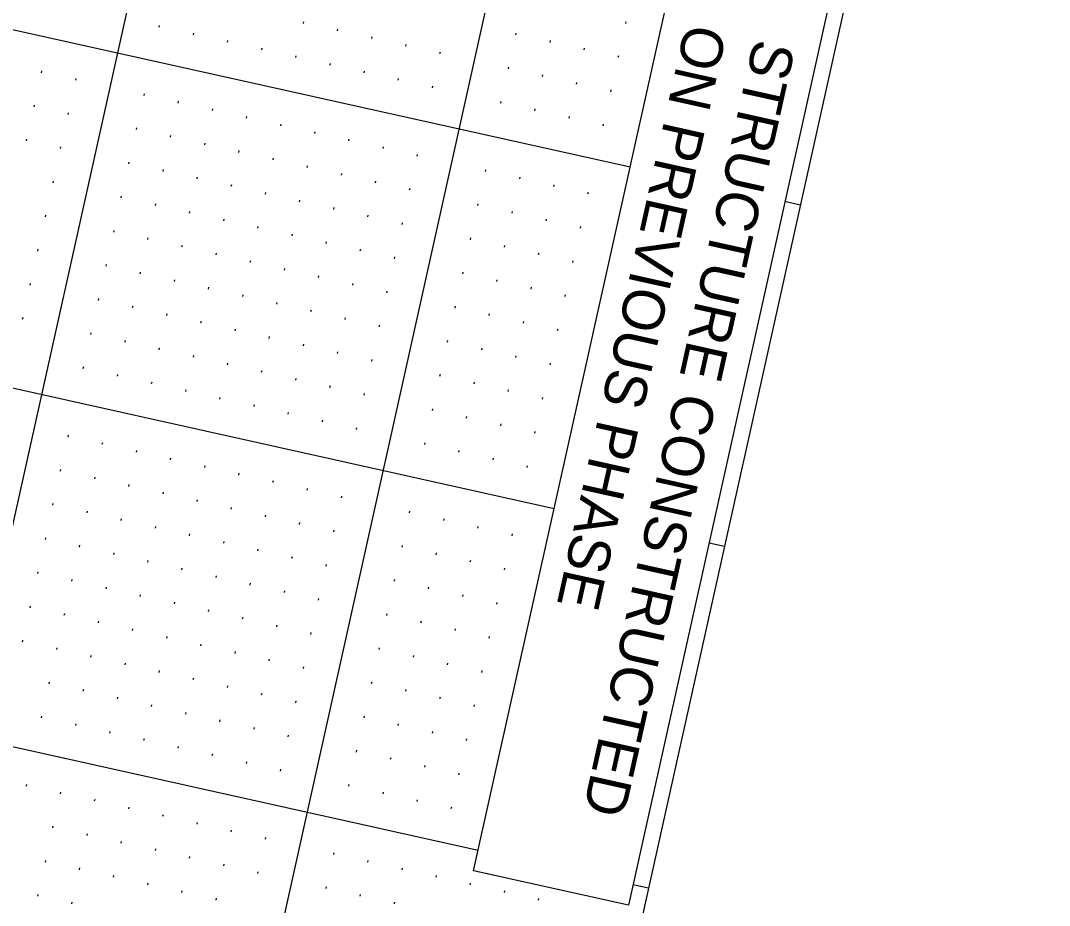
# Model space of a CAD drawing. Extents: x 2149268 to 2150830, y 142155 to 144285.
# Drawn here: x 2149816 to 2149963, y 142509.8 to 142636.2 of the extents above; entities that cross this region are included whole.
import ezdxf

# ---------------------------------------------------------------- set-up
doc = ezdxf.new("R2010")
doc.units = 0
for name, color, linetype in [('PR_Grading_Txt', 7, 'Continuous'), ('PR_Misc_Improvement', 7, 'Continuous'), ('SHT_Profile_Grid_Major', 7, 'Continuous'), ('SHT_Profile_Grid_Minor', 7, 'Continuous'), ('SHT_Sheet_Border', 7, 'Continuous')]:
    doc.layers.add(name, color=color, linetype=linetype)

msp = doc.modelspace()

# ---------------------------------------------------------------- linework, layer by layer
at = {"layer": 'PR_Misc_Improvement'}
msp.add_lwpolyline([(2149936.73, 142662.14), (2149902.85, 142509.8), (2149880.72, 142514.72), (2149914.6, 142667.07)], close=True, dxfattribs=at)
at = {"layer": 'SHT_Profile_Grid_Major'}
for p, q in [((2150109.25, 143888.4), (2149767.39, 142350.95)), ((2150158.06, 143877.55), (2149816.2, 142340.1)), ((2149439.33, 142718.42), (2149903.09, 142615.3)), ((2149452.88, 142664.18), (2149892.23, 142566.49)), ((2149442.03, 142615.38), (2149881.38, 142517.68)), ((2149925.22, 142610.38), (2149927.41, 142609.89)), ((2149914.37, 142561.57), (2149916.56, 142561.08)), ((2149903.51, 142512.76), (2149905.7, 142512.27))]:
    msp.add_line(p, q, dxfattribs=at)
at = {"layer": 'SHT_Profile_Grid_Minor'}
for p, q in [((2149856.4, 142636.05), (2149856.34, 142635.81)), ((2149902.49, 142636.05), (2149902.44, 142635.8)), ((2149835.79, 142635.51), (2149835.73, 142635.27)), ((2149861.28, 142634.97), (2149861.22, 142634.72)), ((2149840.67, 142634.43), (2149840.61, 142634.18)), ((2149845.55, 142633.34), (2149845.49, 142633.1)), ((2149866.16, 142633.88), (2149866.1, 142633.64)), ((2149886.77, 142634.42), (2149886.71, 142634.18)), ((2149891.65, 142633.34), (2149891.59, 142633.09)), ((2149850.43, 142632.26), (2149850.38, 142632.01)), ((2149871.04, 142632.8), (2149870.98, 142632.55)), ((2149875.92, 142631.71), (2149875.86, 142631.47)), ((2149896.53, 142632.25), (2149896.47, 142632.01)), ((2149855.31, 142631.17), (2149855.26, 142630.93)), ((2149901.41, 142631.17), (2149901.35, 142630.92)), ((2149818.97, 142629.01), (2149818.92, 142628.76)), ((2149860.19, 142630.09), (2149860.14, 142629.84)), ((2149865.07, 142629), (2149865.02, 142628.76)), ((2149885.68, 142629.54), (2149885.63, 142629.3)), ((2149823.86, 142627.92), (2149823.8, 142627.68)), ((2149869.95, 142627.92), (2149869.9, 142627.67)), ((2149890.56, 142628.46), (2149890.51, 142628.21)), ((2149895.44, 142627.37), (2149895.39, 142627.13)), ((2149833.62, 142625.75), (2149833.56, 142625.51)), ((2149874.83, 142626.83), (2149874.78, 142626.59)), ((2149900.32, 142626.29), (2149900.27, 142626.04)), ((2149838.5, 142624.67), (2149838.44, 142624.42)), ((2149884.6, 142624.66), (2149884.54, 142624.42)), ((2149817.89, 142624.13), (2149817.84, 142623.88)), ((2149822.77, 142623.04), (2149822.72, 142622.8)), ((2149843.38, 142623.58), (2149843.32, 142623.34)), ((2149889.48, 142623.58), (2149889.42, 142623.33)), ((2149848.26, 142622.5), (2149848.21, 142622.25)), ((2149853.14, 142621.41), (2149853.09, 142621.17)), ((2149894.36, 142622.49), (2149894.3, 142622.25)), ((2149899.24, 142621.41), (2149899.18, 142621.16)), ((2149832.53, 142620.87), (2149832.48, 142620.63)), ((2149858.02, 142620.33), (2149857.97, 142620.08)), ((2149816.8, 142619.25), (2149816.75, 142619)), ((2149837.41, 142619.79), (2149837.36, 142619.54)), ((2149842.29, 142618.7), (2149842.24, 142618.46)), ((2149862.9, 142619.24), (2149862.85, 142619)), ((2149821.68, 142618.16), (2149821.63, 142617.92)), ((2149847.17, 142617.62), (2149847.12, 142617.37)), ((2149867.78, 142618.16), (2149867.73, 142617.91)), ((2149872.66, 142617.07), (2149872.61, 142616.83)), ((2149831.45, 142615.99), (2149831.39, 142615.75)), ((2149852.05, 142616.53), (2149852, 142616.29)), ((2149856.94, 142615.44), (2149856.88, 142615.2)), ((2149836.33, 142614.91), (2149836.27, 142614.66)), ((2149861.82, 142614.36), (2149861.76, 142614.12)), ((2149882.43, 142614.9), (2149882.37, 142614.66)), ((2149820.6, 142613.28), (2149820.55, 142613.04)), ((2149841.21, 142613.82), (2149841.15, 142613.58)), ((2149846.09, 142612.73), (2149846.03, 142612.49)), ((2149866.7, 142613.27), (2149866.64, 142613.03)), ((2149887.31, 142613.81), (2149887.25, 142613.57)), ((2149892.19, 142612.73), (2149892.13, 142612.48)), ((2149830.36, 142611.11), (2149830.31, 142610.87)), ((2149850.97, 142611.65), (2149850.92, 142611.41)), ((2149871.58, 142612.19), (2149871.52, 142611.95)), ((2149897.07, 142611.64), (2149897.01, 142611.4)), ((2149835.24, 142610.02), (2149835.19, 142609.78)), ((2149855.85, 142610.56), (2149855.8, 142610.32)), ((2149881.34, 142610.02), (2149881.29, 142609.77)), ((2149819.51, 142608.4), (2149819.46, 142608.16)), ((2149840.12, 142608.94), (2149840.07, 142608.7)), ((2149860.73, 142609.48), (2149860.68, 142609.23)), ((2149865.61, 142608.39), (2149865.56, 142608.15)), ((2149886.22, 142608.93), (2149886.17, 142608.69)), ((2149845, 142607.85), (2149844.95, 142607.61)), ((2149849.88, 142606.77), (2149849.83, 142606.52)), ((2149870.49, 142607.31), (2149870.44, 142607.06)), ((2149891.1, 142607.85), (2149891.05, 142607.6)), ((2149895.98, 142606.76), (2149895.93, 142606.52)), ((2149829.28, 142606.23), (2149829.22, 142605.98)), ((2149854.77, 142605.68), (2149854.71, 142605.44)), ((2149834.16, 142605.14), (2149834.1, 142604.9)), ((2149839.04, 142604.06), (2149838.98, 142603.81)), ((2149859.65, 142604.6), (2149859.59, 142604.35)), ((2149880.25, 142605.14), (2149880.2, 142604.89)), ((2149885.14, 142604.05), (2149885.08, 142603.81)), ((2149818.43, 142603.52), (2149818.37, 142603.27)), ((2149843.92, 142602.97), (2149843.86, 142602.73)), ((2149864.53, 142603.51), (2149864.47, 142603.27)), ((2149869.41, 142602.43), (2149869.35, 142602.18)), ((2149890.02, 142602.97), (2149889.96, 142602.72)), ((2149828.19, 142601.35), (2149828.14, 142601.1)), ((2149848.8, 142601.89), (2149848.74, 142601.64)), ((2149853.68, 142600.8), (2149853.63, 142600.56)), ((2149894.9, 142601.88), (2149894.84, 142601.64)), ((2149833.07, 142600.26), (2149833.02, 142600.02)), ((2149858.56, 142599.72), (2149858.51, 142599.47)), ((2149879.17, 142600.26), (2149879.11, 142600.01)), ((2149817.34, 142598.64), (2149817.29, 142598.39)), ((2149837.95, 142599.18), (2149837.9, 142598.93)), ((2149842.83, 142598.09), (2149842.78, 142597.85)), ((2149863.44, 142598.63), (2149863.39, 142598.39)), ((2149884.05, 142599.17), (2149884, 142598.93)), ((2149888.93, 142598.09), (2149888.88, 142597.84)), ((2149827.11, 142596.47), (2149827.05, 142596.22)), ((2149847.71, 142597.01), (2149847.66, 142596.76)), ((2149868.32, 142597.55), (2149868.27, 142597.3)), ((2149893.81, 142597), (2149893.76, 142596.76)), ((2149831.99, 142595.38), (2149831.93, 142595.14)), ((2149852.59, 142595.92), (2149852.54, 142595.68)), ((2149878.08, 142595.38), (2149878.03, 142595.13)), ((2149816.26, 142593.76), (2149816.2, 142593.51)), ((2149836.87, 142594.3), (2149836.81, 142594.05)), ((2149857.48, 142594.84), (2149857.42, 142594.59)), ((2149862.36, 142593.75), (2149862.3, 142593.51)), ((2149882.96, 142594.29), (2149882.91, 142594.05)), ((2149841.75, 142593.21), (2149841.69, 142592.97)), ((2149846.63, 142592.13), (2149846.57, 142591.88)), ((2149867.24, 142592.67), (2149867.18, 142592.42)), ((2149887.85, 142593.21), (2149887.79, 142592.96)), ((2149892.73, 142592.12), (2149892.67, 142591.88)), ((2149826.02, 142591.59), (2149825.97, 142591.34)), ((2149830.9, 142590.5), (2149830.85, 142590.26)), ((2149851.51, 142591.04), (2149851.46, 142590.8)), ((2149877, 142590.5), (2149876.94, 142590.25)), ((2149835.78, 142589.42), (2149835.73, 142589.17)), ((2149856.39, 142589.96), (2149856.34, 142589.71)), ((2149881.88, 142589.41), (2149881.83, 142589.17)), ((2149840.66, 142588.33), (2149840.61, 142588.09)), ((2149861.27, 142588.87), (2149861.22, 142588.63)), ((2149866.15, 142587.79), (2149866.1, 142587.54)), ((2149886.76, 142588.32), (2149886.71, 142588.08)), ((2149824.93, 142586.71), (2149824.88, 142586.46)), ((2149845.54, 142587.25), (2149845.49, 142587)), ((2149850.42, 142586.16), (2149850.37, 142585.92)), ((2149891.64, 142587.24), (2149891.59, 142587)), ((2149829.82, 142585.62), (2149829.76, 142585.38)), ((2149855.3, 142585.07), (2149855.25, 142584.83)), ((2149875.91, 142585.61), (2149875.86, 142585.37)), ((2149834.7, 142584.54), (2149834.64, 142584.29)), ((2149839.58, 142583.45), (2149839.52, 142583.21)), ((2149860.19, 142583.99), (2149860.13, 142583.75)), ((2149880.79, 142584.53), (2149880.74, 142584.29)), ((2149885.67, 142583.44), (2149885.62, 142583.2)), ((2149844.46, 142582.36), (2149844.4, 142582.12)), ((2149865.07, 142582.9), (2149865.01, 142582.66)), ((2149890.56, 142582.36), (2149890.5, 142582.11)), ((2149849.34, 142581.28), (2149849.28, 142581.04)), ((2149854.22, 142580.19), (2149854.17, 142579.95)), ((2149874.83, 142580.73), (2149874.77, 142580.49)), ((2149859.1, 142579.11), (2149859.05, 142578.86)), ((2149879.71, 142579.65), (2149879.65, 142579.4)), ((2149863.98, 142578.02), (2149863.93, 142577.78)), ((2149884.59, 142578.56), (2149884.54, 142578.32)), ((2149889.47, 142577.48), (2149889.42, 142577.23)), ((2149822.76, 142576.94), (2149822.71, 142576.7)), ((2149827.65, 142575.86), (2149827.59, 142575.61)), ((2149873.74, 142575.85), (2149873.69, 142575.61)), ((2149832.53, 142574.77), (2149832.47, 142574.53)), ((2149878.62, 142574.77), (2149878.57, 142574.52)), ((2149837.41, 142573.69), (2149837.35, 142573.44)), ((2149883.5, 142573.68), (2149883.45, 142573.44)), ((2149821.68, 142572.06), (2149821.62, 142571.82)), ((2149842.29, 142572.6), (2149842.23, 142572.36)), ((2149847.17, 142571.52), (2149847.11, 142571.27)), ((2149888.39, 142572.6), (2149888.33, 142572.35)), ((2149826.56, 142570.98), (2149826.51, 142570.73)), ((2149831.44, 142569.89), (2149831.39, 142569.65)), ((2149852.05, 142570.43), (2149851.99, 142570.19)), ((2149836.32, 142568.81), (2149836.27, 142568.56)), ((2149856.93, 142569.35), (2149856.88, 142569.1)), ((2149820.59, 142567.18), (2149820.54, 142566.94)), ((2149841.2, 142567.72), (2149841.15, 142567.48)), ((2149861.81, 142568.26), (2149861.76, 142568.02)), ((2149825.47, 142566.1), (2149825.42, 142565.85)), ((2149846.08, 142566.64), (2149846.03, 142566.39)), ((2149850.96, 142565.55), (2149850.91, 142565.31)), ((2149871.57, 142566.09), (2149871.52, 142565.85)), ((2149830.36, 142565.01), (2149830.3, 142564.77)), ((2149855.84, 142564.47), (2149855.79, 142564.22)), ((2149876.45, 142565.01), (2149876.4, 142564.76)), ((2149835.24, 142563.93), (2149835.18, 142563.68)), ((2149840.12, 142562.84), (2149840.06, 142562.6)), ((2149860.73, 142563.38), (2149860.67, 142563.14)), ((2149881.33, 142563.92), (2149881.28, 142563.68)), ((2149886.21, 142562.84), (2149886.16, 142562.59)), ((2149819.51, 142562.3), (2149819.45, 142562.06)), ((2149824.39, 142561.22), (2149824.33, 142560.97)), ((2149845, 142561.76), (2149844.94, 142561.51)), ((2149870.49, 142561.21), (2149870.43, 142560.97)), ((2149829.27, 142560.13), (2149829.22, 142559.89)), ((2149849.88, 142560.67), (2149849.82, 142560.43)), ((2149854.76, 142559.59), (2149854.7, 142559.34)), ((2149875.37, 142560.13), (2149875.31, 142559.88)), ((2149834.15, 142559.05), (2149834.1, 142558.8)), ((2149859.64, 142558.5), (2149859.59, 142558.26)), ((2149880.25, 142559.04), (2149880.19, 142558.8)), ((2149818.42, 142557.42), (2149818.37, 142557.18)), ((2149839.03, 142557.96), (2149838.98, 142557.72)), ((2149843.91, 142556.88), (2149843.86, 142556.63)), ((2149885.13, 142557.95), (2149885.08, 142557.71)), ((2149823.3, 142556.34), (2149823.25, 142556.09)), ((2149828.18, 142555.25), (2149828.13, 142555.01)), ((2149848.79, 142555.79), (2149848.74, 142555.55)), ((2149869.4, 142556.33), (2149869.35, 142556.09)), ((2149874.28, 142555.24), (2149874.23, 142555)), ((2149833.07, 142554.17), (2149833.01, 142553.92)), ((2149853.67, 142554.7), (2149853.62, 142554.46)), ((2149879.16, 142554.16), (2149879.11, 142553.92)), ((2149817.34, 142552.54), (2149817.28, 142552.3)), ((2149837.95, 142553.08), (2149837.89, 142552.84)), ((2149858.55, 142553.62), (2149858.5, 142553.38)), ((2149884.04, 142553.07), (2149883.99, 142552.83)), ((2149822.22, 142551.45), (2149822.16, 142551.21)), ((2149842.83, 142551.99), (2149842.77, 142551.75)), ((2149847.71, 142550.91), (2149847.65, 142550.67)), ((2149868.32, 142551.45), (2149868.26, 142551.2)), ((2149827.1, 142550.37), (2149827.05, 142550.13)), ((2149831.98, 142549.28), (2149831.93, 142549.04)), ((2149852.59, 142549.82), (2149852.53, 142549.58)), ((2149873.2, 142550.36), (2149873.14, 142550.12)), ((2149878.08, 142549.28), (2149878.02, 142549.03)), ((2149836.86, 142548.2), (2149836.81, 142547.96)), ((2149857.47, 142548.74), (2149857.42, 142548.49)), ((2149882.96, 142548.19), (2149882.9, 142547.95)), ((2149816.25, 142547.66), (2149816.2, 142547.42)), ((2149821.13, 142546.57), (2149821.08, 142546.33)), ((2149841.74, 142547.11), (2149841.69, 142546.87)), ((2149867.23, 142546.57), (2149867.18, 142546.32)), ((2149826.01, 142545.49), (2149825.96, 142545.24)), ((2149846.62, 142546.03), (2149846.57, 142545.78)), ((2149851.5, 142544.94), (2149851.45, 142544.7)), ((2149872.11, 142545.48), (2149872.06, 142545.24)), ((2149830.89, 142544.4), (2149830.84, 142544.16)), ((2149856.38, 142543.86), (2149856.33, 142543.61)), ((2149876.99, 142544.4), (2149876.94, 142544.15)), ((2149835.78, 142543.32), (2149835.72, 142543.07)), ((2149840.66, 142542.23), (2149840.6, 142541.99)), ((2149881.87, 142543.31), (2149881.82, 142543.07)), ((2149820.05, 142541.69), (2149819.99, 142541.45)), ((2149824.93, 142540.61), (2149824.87, 142540.36)), ((2149845.54, 142541.15), (2149845.48, 142540.9)), ((2149866.15, 142541.69), (2149866.09, 142541.44)), ((2149871.03, 142540.6), (2149870.97, 142540.36)), ((2149829.81, 142539.52), (2149829.76, 142539.28)), ((2149850.42, 142540.06), (2149850.36, 142539.82)), ((2149855.3, 142538.98), (2149855.24, 142538.73)), ((2149875.91, 142539.52), (2149875.85, 142539.27)), ((2149834.69, 142538.44), (2149834.64, 142538.19)), ((2149880.79, 142538.43), (2149880.73, 142538.19)), ((2149818.96, 142536.81), (2149818.91, 142536.57)), ((2149839.57, 142537.35), (2149839.52, 142537.11)), ((2149844.45, 142536.27), (2149844.4, 142536.02)), ((2149865.06, 142536.81), (2149865.01, 142536.56)), ((2149823.84, 142535.73), (2149823.79, 142535.48)), ((2149828.72, 142534.64), (2149828.67, 142534.4)), ((2149849.33, 142535.18), (2149849.28, 142534.94)), ((2149869.94, 142535.72), (2149869.89, 142535.48)), ((2149874.82, 142534.64), (2149874.77, 142534.39)), ((2149833.61, 142533.56), (2149833.55, 142533.31)), ((2149854.21, 142534.1), (2149854.16, 142533.85)), ((2149879.7, 142533.55), (2149879.65, 142533.31)), ((2149838.49, 142532.47), (2149838.43, 142532.23)), ((2149863.98, 142531.93), (2149863.92, 142531.68)), ((2149843.37, 142531.39), (2149843.31, 142531.14)), ((2149848.25, 142530.3), (2149848.19, 142530.06)), ((2149868.86, 142530.84), (2149868.8, 142530.6)), ((2149853.13, 142529.22), (2149853.07, 142528.97)), ((2149873.74, 142529.76), (2149873.68, 142529.51)), ((2149878.62, 142528.67), (2149878.56, 142528.43)), ((2149816.79, 142527.05), (2149816.74, 142526.81)), ((2149821.67, 142525.97), (2149821.62, 142525.72)), ((2149862.89, 142527.05), (2149862.84, 142526.8)), ((2149867.77, 142525.96), (2149867.72, 142525.72)), ((2149826.55, 142524.88), (2149826.5, 142524.64)), ((2149872.65, 142524.87), (2149872.6, 142524.63)), ((2149831.43, 142523.8), (2149831.38, 142523.55)), ((2149877.53, 142523.79), (2149877.48, 142523.55)), ((2149836.32, 142522.71), (2149836.26, 142522.47)), ((2149841.2, 142521.62), (2149841.14, 142521.38)), ((2149820.59, 142521.08), (2149820.53, 142520.84)), ((2149825.47, 142520), (2149825.41, 142519.76)), ((2149846.08, 142520.54), (2149846.02, 142520.3)), ((2149830.35, 142518.91), (2149830.3, 142518.67)), ((2149850.96, 142519.45), (2149850.9, 142519.21)), ((2149835.23, 142517.83), (2149835.18, 142517.59)), ((2149860.72, 142517.28), (2149860.67, 142517.04)), ((2149819.5, 142516.2), (2149819.45, 142515.96)), ((2149840.11, 142516.74), (2149840.06, 142516.5)), ((2149844.99, 142515.66), (2149844.94, 142515.41)), ((2149865.6, 142516.2), (2149865.55, 142515.95)), ((2149824.38, 142515.12), (2149824.33, 142514.87)), ((2149829.26, 142514.03), (2149829.21, 142513.79)), ((2149849.87, 142514.57), (2149849.82, 142514.33)), ((2149870.48, 142515.11), (2149870.43, 142514.87)), ((2149875.36, 142514.03), (2149875.31, 142513.78)), ((2149834.14, 142512.95), (2149834.09, 142512.7)), ((2149880.24, 142512.94), (2149880.19, 142512.7)), ((2149818.42, 142511.32), (2149818.36, 142511.08)), ((2149839.03, 142511.86), (2149838.97, 142511.62)), ((2149859.63, 142512.4), (2149859.58, 142512.16)), ((2149864.51, 142511.32), (2149864.46, 142511.07)), ((2149885.12, 142511.86), (2149885.07, 142511.61)), ((2149823.3, 142510.24), (2149823.24, 142509.99)), ((2149843.91, 142510.78), (2149843.85, 142510.53)), ((2149869.4, 142510.23), (2149869.34, 142509.99)), ((2149890, 142510.77), (2149889.95, 142510.53))]:
    msp.add_line(p, q, dxfattribs=at)
at = {"layer": 'SHT_Sheet_Border'}
msp.add_line((2150206.87, 143866.7), (2149865.01, 142329.24), dxfattribs=at)

# ---------------------------------------------------------------- texts
at = {"layer": 'PR_Grading_Txt'}
for s, p in [('ON PREVIOUS PHASE', (2149911.08, 142635.97)), ('STRUCTURE CONSTRUCTED', (2149920.87, 142633.79))]:
    msp.add_text(s, height=6, rotation=257.4638, dxfattribs=at).set_placement(p)

doc.saveas('drawing.dxf')
